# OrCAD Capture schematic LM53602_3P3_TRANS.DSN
size E; title: LM53602 3P3, 3.5 V to 36 V Wide-VIN Synchronous 2.1 MHz; rev: 1.0; note: Datasheet: SNVSA42B      EVM :SNVU470A
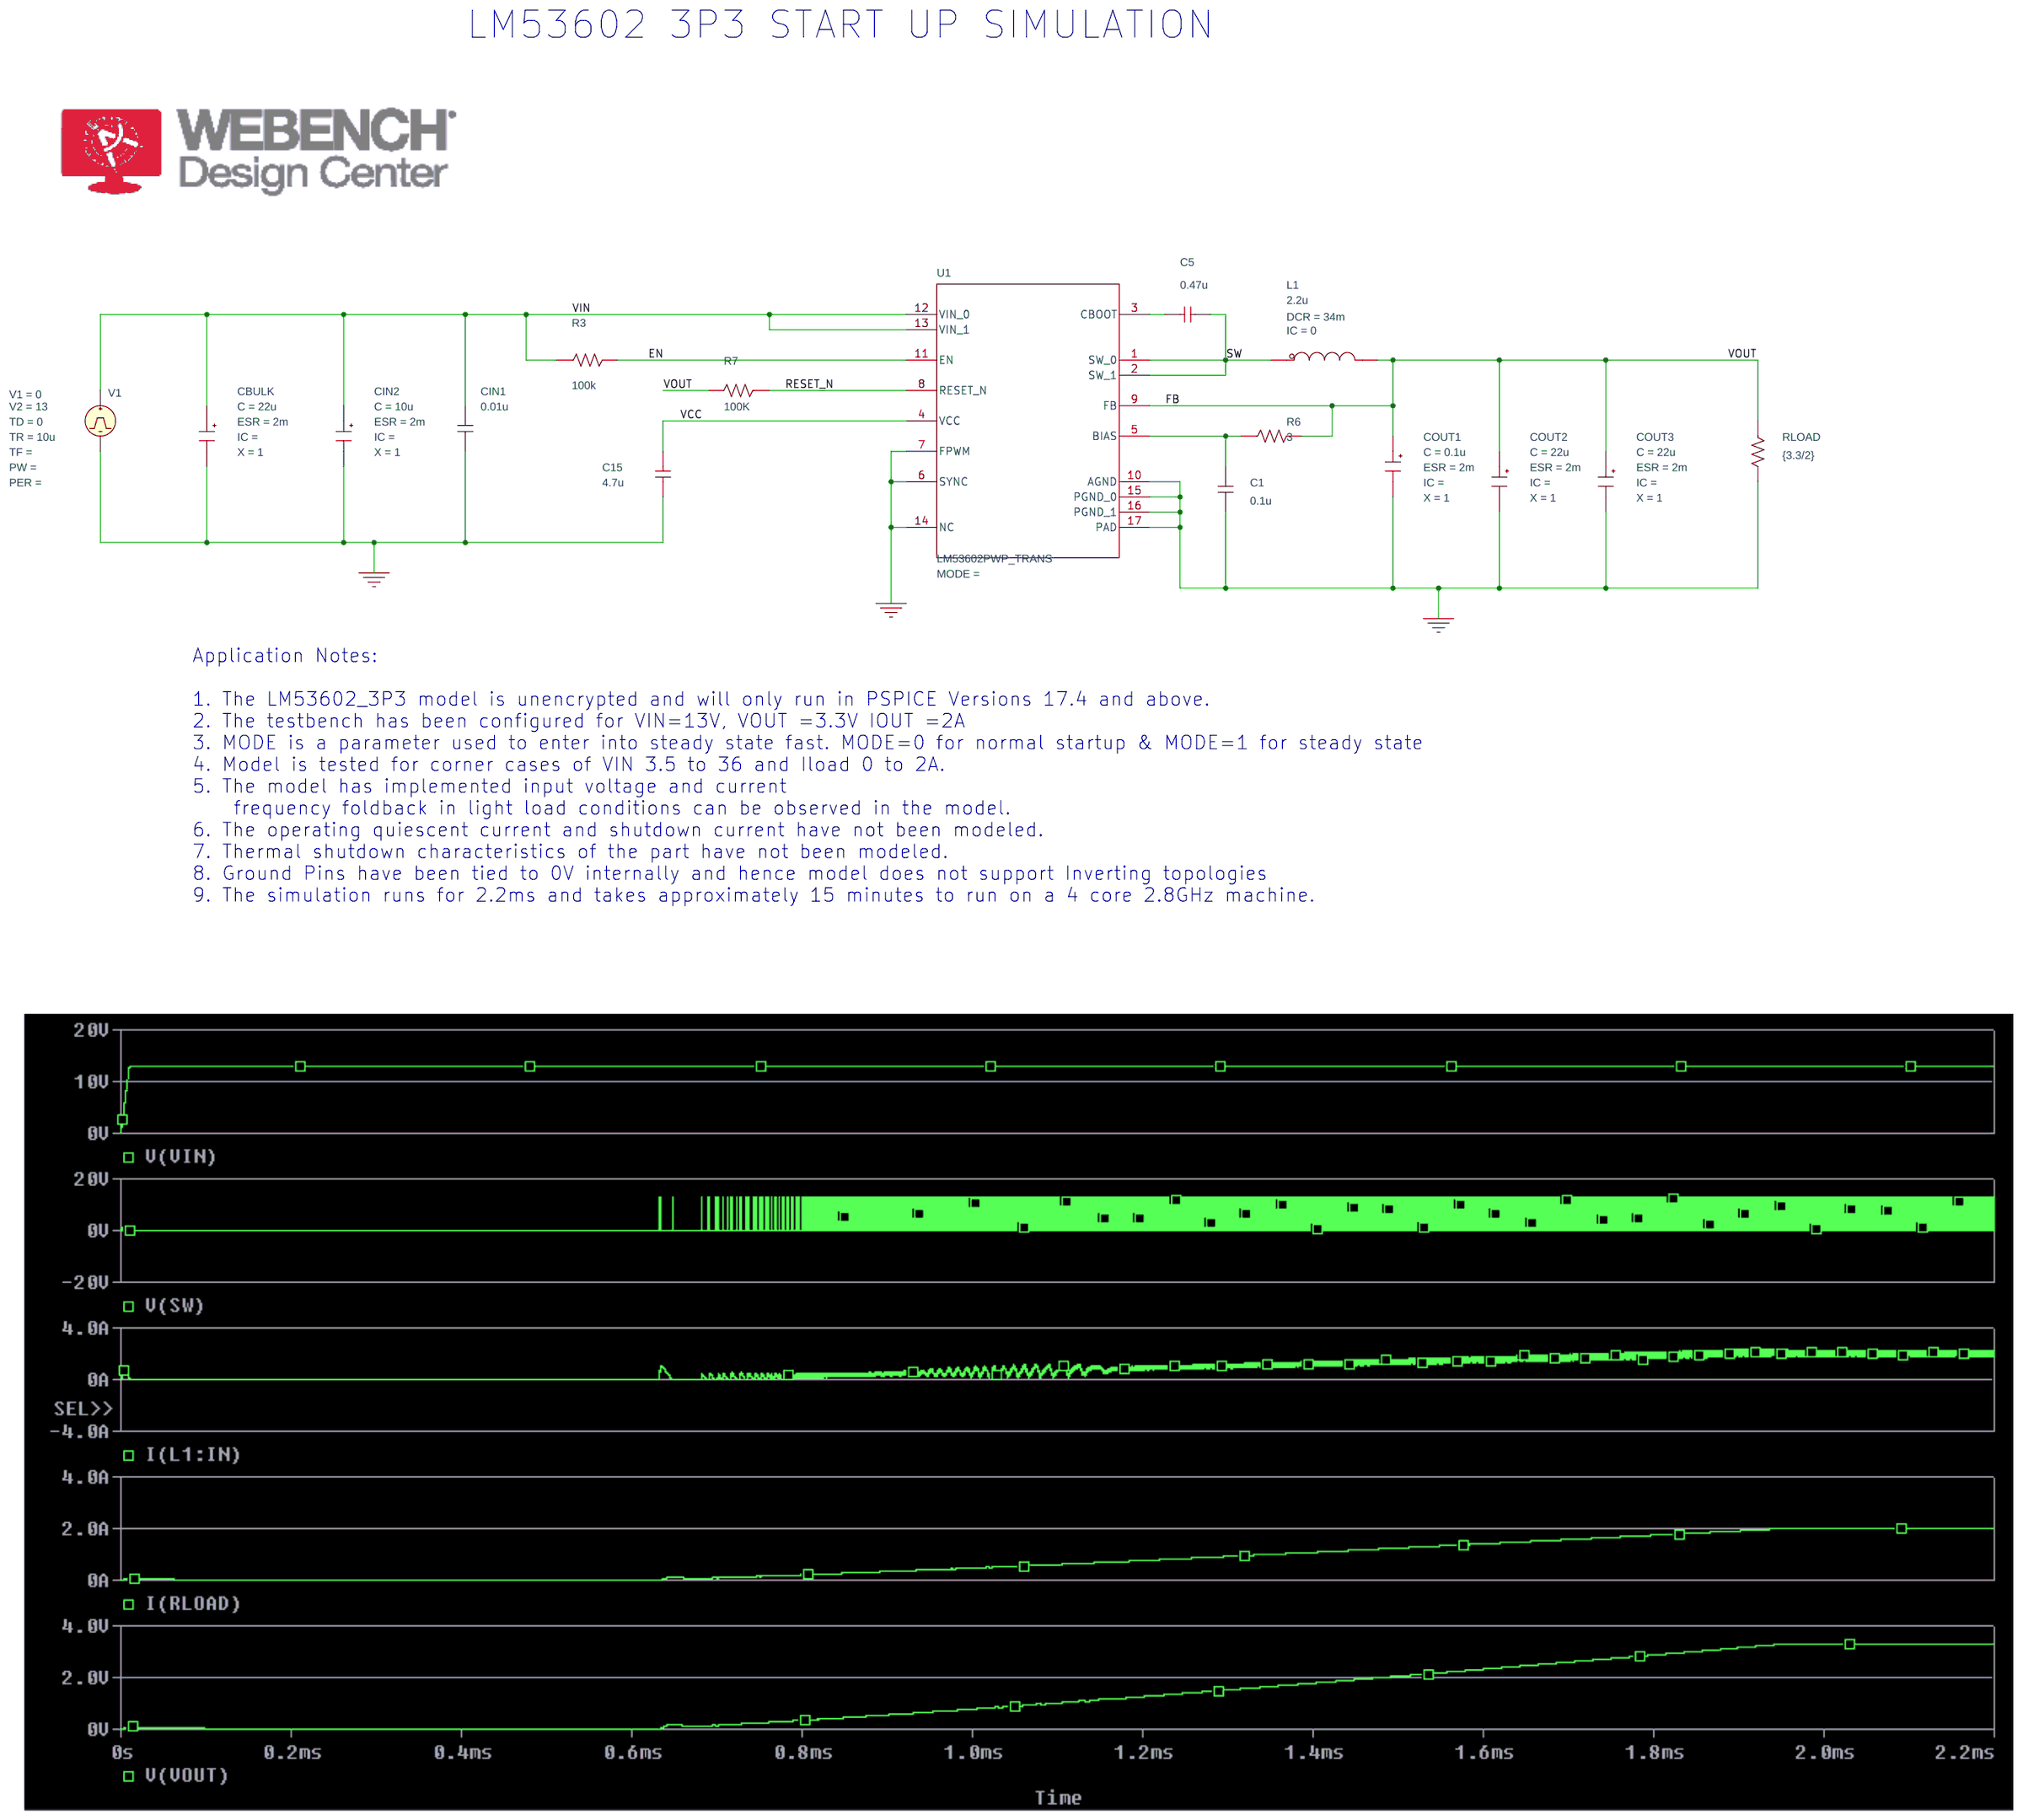
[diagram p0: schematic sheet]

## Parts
C1  0.1u  [RAD/CK05]
C5  0.47u  [RAD/CK05]
C15  4.7u  [RAD/CK05]
CBULK  CESR
CIN1  0.01u  [RAD/CK05]
CIN2  CESR
COUT1  CESR
COUT2  CESR
COUT3  CESR
L1  LDCR
R3  100k  [AX/RC05]
R6  3  [AX/RC05]
R7  100K  [AX/RC05]
RLOAD  {3.3/2}  [AX/RC05]
U1  LM53602PWP_TRANS  [PWP0016H_N]
V1  VPULSE

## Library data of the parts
C1 C5 CIN1 = C
C15 = C: IC: 3.4
CBULK COUT2 COUT3 = CESR_0: C: 22u; ESR: 2m; PSpiceTemplate: X^@REFDES %IN %OUT @MODEL PARAMS:  ?C|C=@C||C=100u|  ?ESR|ESR=@ESR||ESR=0.01| ?X|X=@X||X=2|  ?IC|IC=@IC||IC=2|; X: 1
CIN2 = CESR_0: C: 10u; ESR: 2m; PSpiceTemplate: X^@REFDES %IN %OUT @MODEL PARAMS:  ?C|C=@C||C=100u|  ?ESR|ESR=@ESR||ESR=0.01| ?X|X=@X||X=2|  ?IC|IC=@IC||IC=2|; X: 1
COUT1 = CESR_0: C: 0.1u; ESR: 2m; PSpiceTemplate: X^@REFDES %IN %OUT @MODEL PARAMS:  ?C|C=@C||C=100u|  ?ESR|ESR=@ESR||ESR=0.01| ?X|X=@X||X=2|  ?IC|IC=@IC||IC=2|; X: 1
L1 = LDCR_0: DCR: 34m; IC: 0; L: 2.2u; PSpiceTemplate: X^@REFDES %IN %OUT @MODEL PARAMS:  ?L|L=@L||L=1u|  ?DCR|DCR=@DCR||DCR=0.01| ?IC|IC=@IC||IC=0|
R3 R6 R7 RLOAD = R
U1 = LM53602PWP_TRANS
V1 = VPULSE: TD: 0; TR: 10u; V1: 0; V2: 13

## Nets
VCC: C15.2 U1.4(VCC)
VIN: CBULK.1(IN) CIN1.2 CIN2.1(IN) R3.1 U1.12(VIN_0) U1.13(VIN_1) V1.1(+)
0: C1.1 C15.1 CBULK.3(OUT) CIN1.1 CIN2.3(OUT) COUT1.3(OUT) COUT2.3(OUT) COUT3.3(OUT) RLOAD.2 U1.6(SYNC) U1.7(FPWM) U1.10(AGND) U1.14(NC) U1.15(PGND_0) U1.16(PGND_1) U1.17(PAD) V1.2(-)
EN: R3.2 U1.11(EN)
FB: COUT1.1(IN) COUT2.1(IN) COUT3.1(IN) L1.3(OUT) R6.2 R7.2 RLOAD.1 U1.9(FB)
RESET_N: R7.1 U1.8(RESET_N)
SW: C5.1 L1.1(IN) U1.1(SW_0) U1.2(SW_1)
N16798196: C1.2 R6.1 U1.5(BIAS)
N16798680: C5.2 U1.3(CBOOT)

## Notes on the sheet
- LM53602 3P3 START UP SIMULATION
- Application Notes:
  1. The LM53602_3P3 model is unencrypted and will only run in PSPICE Versions 17.4 and above.
  2. The testbench has been configured for VIN=13V, VOUT =3.3V IOUT =2A
  3. MODE is a parameter used to enter into steady state fast. MODE=0 for normal startup & MODE=1 for steady state
  4. Model is tested for corner cases of VIN 3.5 to 36 and Iload 0 to 2A.
  5. The model has implemented input voltage and current
      frequency foldback in light load conditions can be observed in the model.
  6. The operating quiescent current and shutdown current have not been modeled.
  7. Thermal shutdown characteristics of the part have not been modeled.
  8. Ground Pins have been tied to 0V internally and hence model does not support Inverting topologies
  9. The simulation runs for 2.2ms and takes approximately 15 minutes to run on a 4 core 2.8GHz machine.
